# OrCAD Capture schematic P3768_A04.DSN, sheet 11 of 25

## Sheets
11 0014_USB3.1 HUB: size Custom
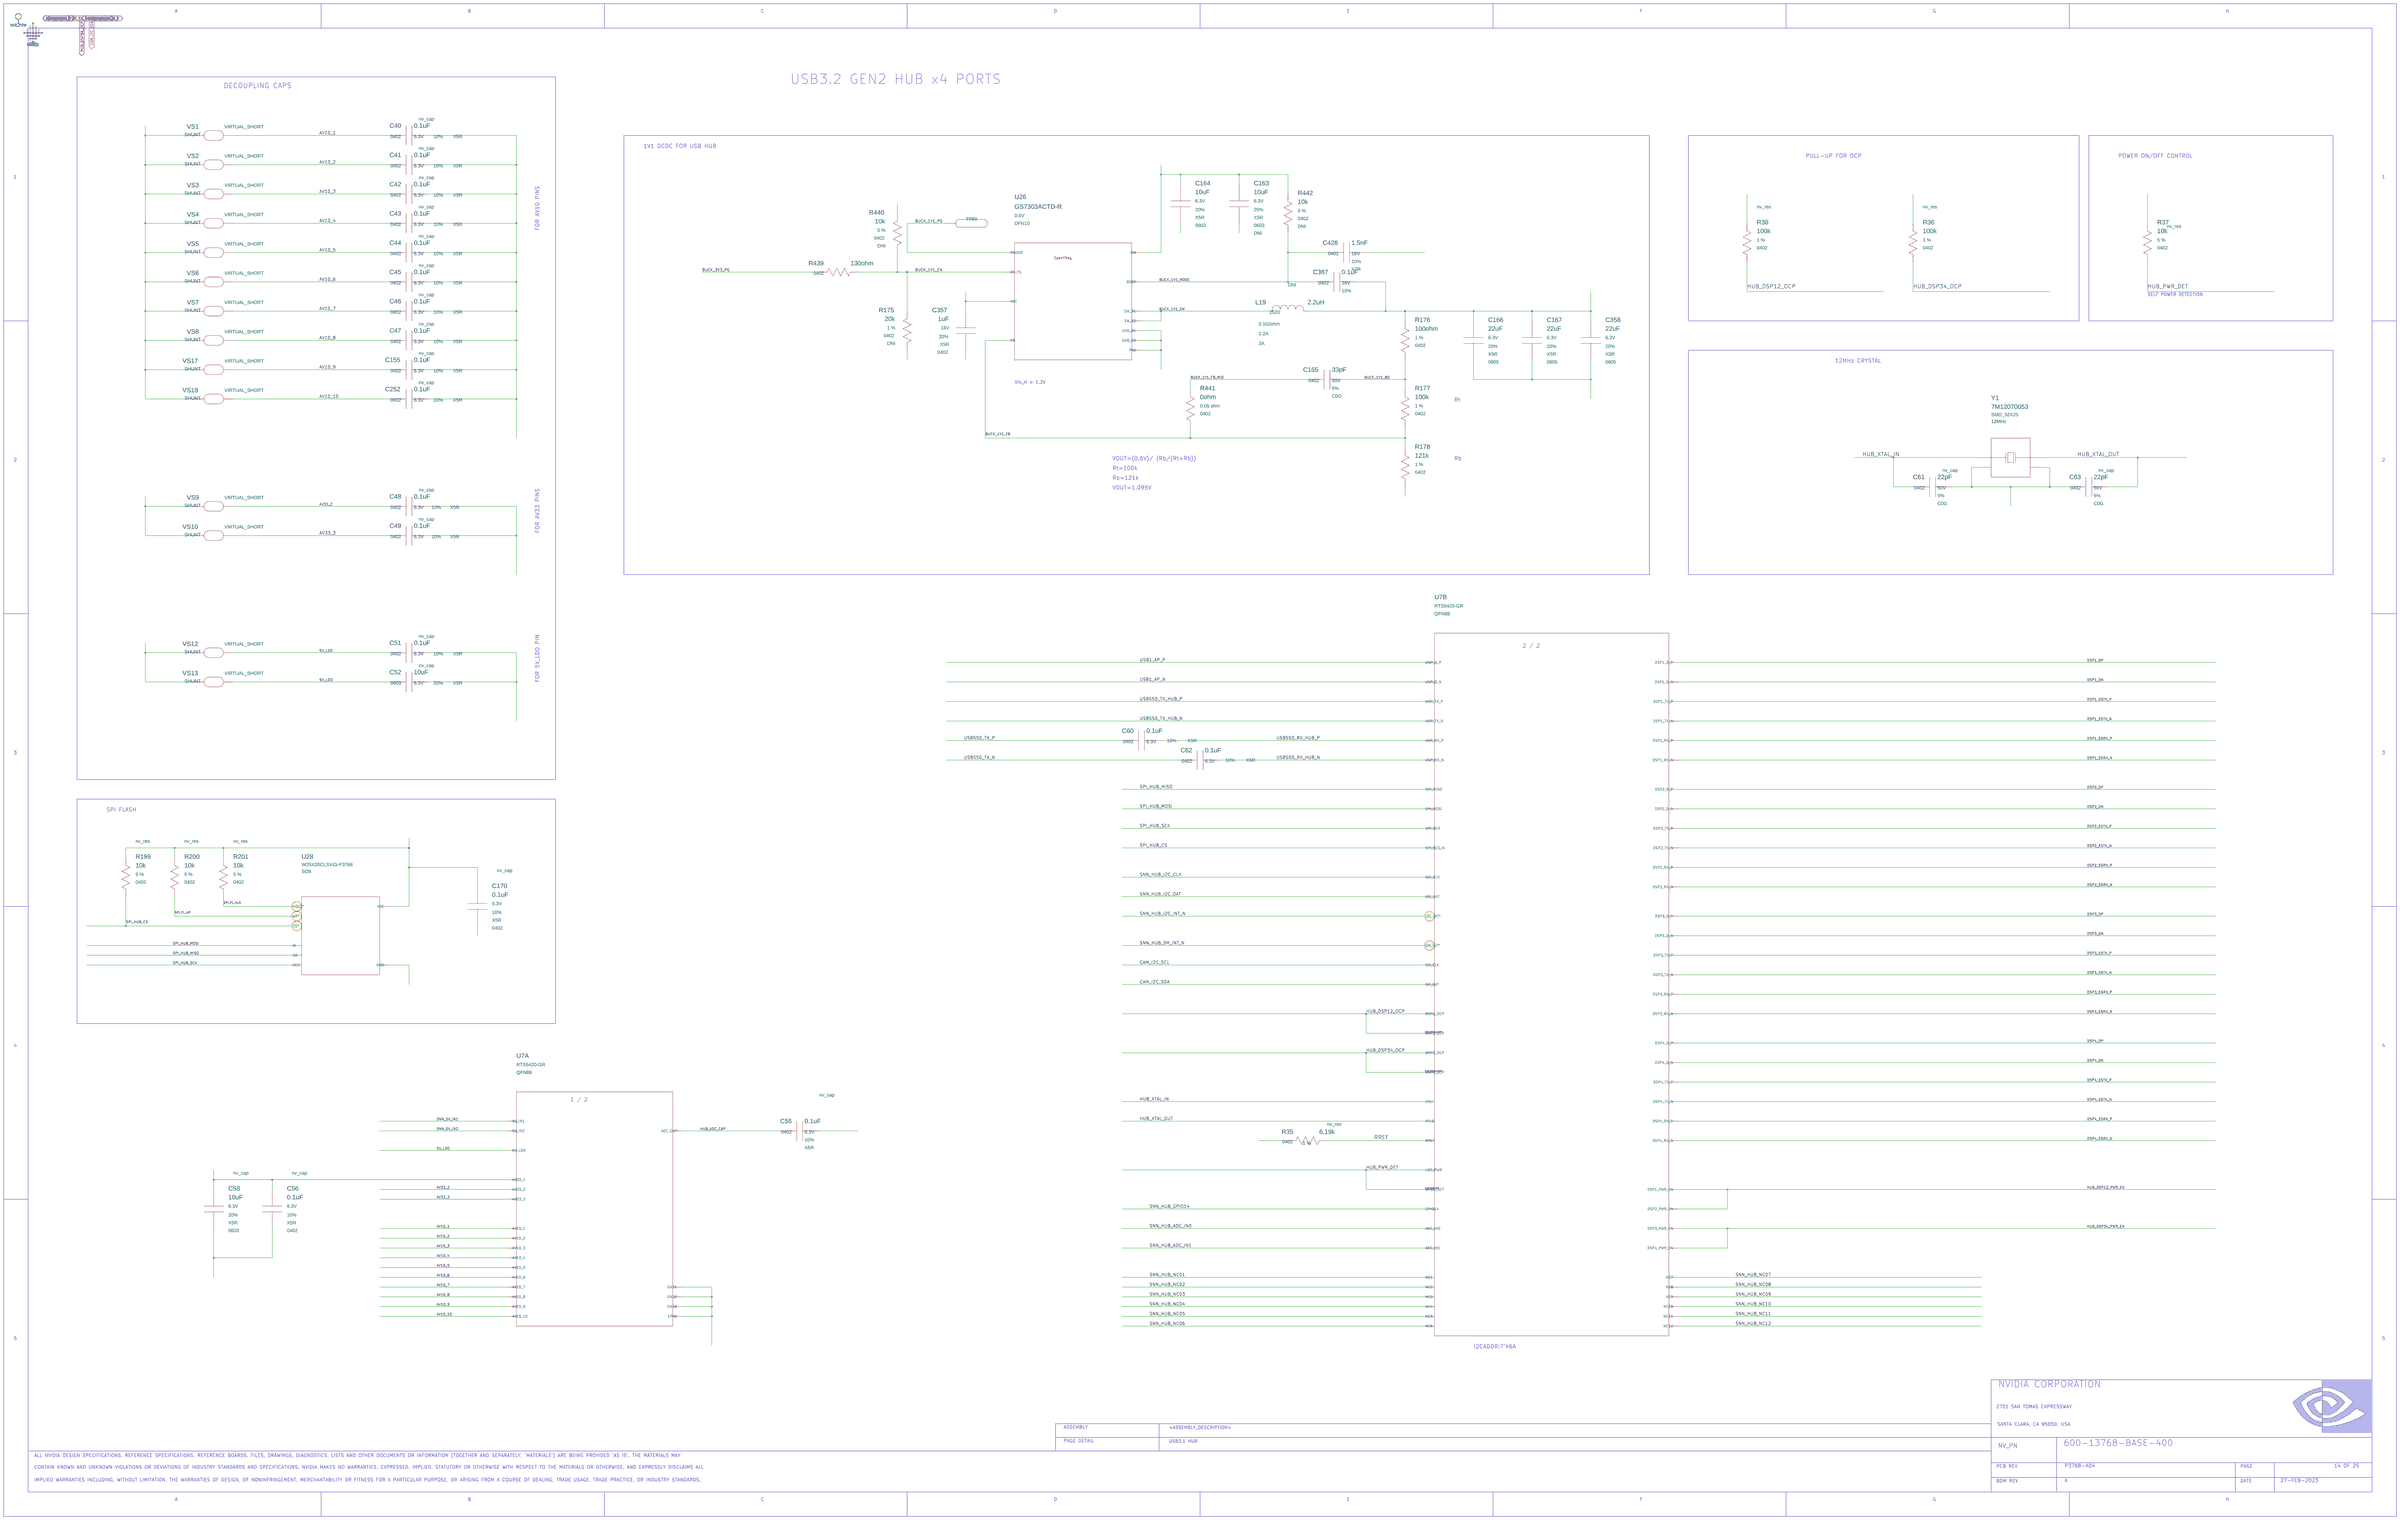
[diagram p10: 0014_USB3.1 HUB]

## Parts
C40  0.1uF  [0402]
C41  0.1uF  [0402]
C42  0.1uF  [0402]
C43  0.1uF  [0402]
C44  0.1uF  [0402]
C45  0.1uF  [0402]
C46  0.1uF  [0402]
C47  0.1uF  [0402]
C48  0.1uF  [0402]
C49  0.1uF  [0402]
C51  0.1uF  [0402]
C52  10uF  [0603]
C55  0.1uF  [0402]
C56  0.1uF  [0402]
C58  10uF  [0603]
C60  0.1uF  [0402]
C61  22pF  [0402]
C62  0.1uF  [0402]
C63  22pF  [0402]
C155  0.1uF  [0402]
C163  10uF  [0603]
C164  10uF  [0603]
C165  33pF  [0402]
C166  22uF  [0805U]
C167  22uF  [0805U]
C170  0.1uF  [0402]
C252  0.1uF  [0402]
C357  1uF  [0402]
C358  22uF  [0805U]
C387  0.1uF  [0402]
C428  1.5nF  [0402]
L19  2.2uH  [IND_NONRKO_SMD_025X020]
R35  6.19k  [0402]
R36  100k  [0402]
R37  10k  [0402]
R38  100k  [0402]
R175  20k  [0402]
R176  100ohm  [0402]
R177  100k  [0402]
R178  121k  [0402]
R199  10k  [0402]
R200  10k  [0402]
R201  10k  [0402]
R439  130ohm  [0402]
R440  10k  [0402]
R441  0ohm  [0402]
R442  10k  [0402]
TP50  LABTESTPOINT  [LTPT071C125D]
U7  U_USB_HUB_RTS5489  [QFN088Q_P040_0100_T069X069]  (sections A,B)
U26  0.6V  [DFN10_P050_030X030_T024X017]
U28  U_MEM_FL_SER_256KX8  [SO08_048X038]
VS1  VIRTUAL_SHORT  [VIRTUAL_SHORT]
VS2  VIRTUAL_SHORT  [VIRTUAL_SHORT]
VS3  VIRTUAL_SHORT  [VIRTUAL_SHORT]
VS4  VIRTUAL_SHORT  [VIRTUAL_SHORT]
VS5  VIRTUAL_SHORT  [VIRTUAL_SHORT]
VS6  VIRTUAL_SHORT  [VIRTUAL_SHORT]
VS7  VIRTUAL_SHORT  [VIRTUAL_SHORT]
VS8  VIRTUAL_SHORT  [VIRTUAL_SHORT]
VS9  VIRTUAL_SHORT  [VIRTUAL_SHORT]
VS10  VIRTUAL_SHORT  [VIRTUAL_SHORT]
VS12  VIRTUAL_SHORT  [VIRTUAL_SHORT]
VS13  VIRTUAL_SHORT  [VIRTUAL_SHORT]
VS17  VIRTUAL_SHORT  [VIRTUAL_SHORT]
VS18  VIRTUAL_SHORT  [VIRTUAL_SHORT]
Y1  12MHz  [XTAL_SMD_4_032X025_D]

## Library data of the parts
C40 = C: ASSEMBLY: USB3_TYPEA; CDS_LIB: discrete; CDS_PART_NAME: C_0402-0.1UF,X5R,10%,6.3V,039-0007-000; CDS_PHYS_PART_NAME: C_0402-0.1UF,X5R,10%,6.3V,039-0007-000-0.1UF,039-0007-000; CDS_SEC: 1; DEVICE_TYPENAME: C_0402-01UFX5R1063V039-0007-000-01UF039-0007-000; DRAWING: @P3768_A04_LIB.P3768_A04(SCH_1):PAGE14; MAT: X5R; MAX_VOLTAGE: 6.3V; NV_PN: 039-0007-000; PATH: I63; PHYS_PAGE: 14; PSPICETEMPLATE: X^@REFDES  %1    %2   @NV_PN; ROT: 0; SEC: 1; SIGNAL_MODEL: nv_cap; TOL: 10%; VER: 2; XY: (-10050,6950)
C41 = C: ASSEMBLY: USB3_TYPEA; CDS_LIB: discrete; CDS_PART_NAME: C_0402-0.1UF,X5R,10%,6.3V,039-0007-000; CDS_PHYS_PART_NAME: C_0402-0.1UF,X5R,10%,6.3V,039-0007-000-0.1UF,039-0007-000; CDS_SEC: 1; DEVICE_TYPENAME: C_0402-01UFX5R1063V039-0007-000-01UF039-0007-000; DRAWING: @P3768_A04_LIB.P3768_A04(SCH_1):PAGE14; MAT: X5R; MAX_VOLTAGE: 6.3V; NV_PN: 039-0007-000; PATH: I64; PHYS_PAGE: 14; PSPICETEMPLATE: X^@REFDES  %1    %2   @NV_PN; ROT: 0; SEC: 1; SIGNAL_MODEL: nv_cap; TOL: 10%; VER: 2; XY: (-10050,6800)
C42 = C: ASSEMBLY: USB3_TYPEA; CDS_LIB: discrete; CDS_PART_NAME: C_0402-0.1UF,X5R,10%,6.3V,039-0007-000; CDS_PHYS_PART_NAME: C_0402-0.1UF,X5R,10%,6.3V,039-0007-000-0.1UF,039-0007-000; CDS_SEC: 1; DEVICE_TYPENAME: C_0402-01UFX5R1063V039-0007-000-01UF039-0007-000; DRAWING: @P3768_A04_LIB.P3768_A04(SCH_1):PAGE14; MAT: X5R; MAX_VOLTAGE: 6.3V; NV_PN: 039-0007-000; PATH: I65; PHYS_PAGE: 14; PSPICETEMPLATE: X^@REFDES  %1    %2   @NV_PN; ROT: 0; SEC: 1; SIGNAL_MODEL: nv_cap; TOL: 10%; VER: 2; XY: (-10050,6650)
C43 = C: ASSEMBLY: USB3_TYPEA; CDS_LIB: discrete; CDS_PART_NAME: C_0402-0.1UF,X5R,10%,6.3V,039-0007-000; CDS_PHYS_PART_NAME: C_0402-0.1UF,X5R,10%,6.3V,039-0007-000-0.1UF,039-0007-000; CDS_SEC: 1; DEVICE_TYPENAME: C_0402-01UFX5R1063V039-0007-000-01UF039-0007-000; DRAWING: @P3768_A04_LIB.P3768_A04(SCH_1):PAGE14; MAT: X5R; MAX_VOLTAGE: 6.3V; NV_PN: 039-0007-000; PATH: I67; PHYS_PAGE: 14; PSPICETEMPLATE: X^@REFDES  %1    %2   @NV_PN; ROT: 0; SEC: 1; SIGNAL_MODEL: nv_cap; TOL: 10%; VER: 2; XY: (-10050,6500)
C44 = C: ASSEMBLY: USB3_TYPEA; CDS_LIB: discrete; CDS_PART_NAME: C_0402-0.1UF,X5R,10%,6.3V,039-0007-000; CDS_PHYS_PART_NAME: C_0402-0.1UF,X5R,10%,6.3V,039-0007-000-0.1UF,039-0007-000; CDS_SEC: 1; DEVICE_TYPENAME: C_0402-01UFX5R1063V039-0007-000-01UF039-0007-000; DRAWING: @P3768_A04_LIB.P3768_A04(SCH_1):PAGE14; MAT: X5R; MAX_VOLTAGE: 6.3V; NV_PN: 039-0007-000; PATH: I66; PHYS_PAGE: 14; PSPICETEMPLATE: X^@REFDES  %1    %2   @NV_PN; ROT: 0; SEC: 1; SIGNAL_MODEL: nv_cap; TOL: 10%; VER: 2; XY: (-10050,6350)
C45 = C: ASSEMBLY: USB3_TYPEA; CDS_LIB: discrete; CDS_PART_NAME: C_0402-0.1UF,X5R,10%,6.3V,039-0007-000; CDS_PHYS_PART_NAME: C_0402-0.1UF,X5R,10%,6.3V,039-0007-000-0.1UF,039-0007-000; CDS_SEC: 1; DEVICE_TYPENAME: C_0402-01UFX5R1063V039-0007-000-01UF039-0007-000; DRAWING: @P3768_A04_LIB.P3768_A04(SCH_1):PAGE14; MAT: X5R; MAX_VOLTAGE: 6.3V; NV_PN: 039-0007-000; PATH: I70; PHYS_PAGE: 14; PSPICETEMPLATE: X^@REFDES  %1    %2   @NV_PN; ROT: 0; SEC: 1; SIGNAL_MODEL: nv_cap; TOL: 10%; VER: 2; XY: (-10050,6200)
C46 = C: ASSEMBLY: USB3_TYPEA; CDS_LIB: discrete; CDS_PART_NAME: C_0402-0.1UF,X5R,10%,6.3V,039-0007-000; CDS_PHYS_PART_NAME: C_0402-0.1UF,X5R,10%,6.3V,039-0007-000-0.1UF,039-0007-000; CDS_SEC: 1; DEVICE_TYPENAME: C_0402-01UFX5R1063V039-0007-000-01UF039-0007-000; DRAWING: @P3768_A04_LIB.P3768_A04(SCH_1):PAGE14; MAT: X5R; MAX_VOLTAGE: 6.3V; NV_PN: 039-0007-000; PATH: I71; PHYS_PAGE: 14; PSPICETEMPLATE: X^@REFDES  %1    %2   @NV_PN; ROT: 0; SEC: 1; SIGNAL_MODEL: nv_cap; TOL: 10%; VER: 2; XY: (-10050,6050)
C47 = C: ASSEMBLY: USB3_TYPEA; CDS_LIB: discrete; CDS_PART_NAME: C_0402-0.1UF,X5R,10%,6.3V,039-0007-000; CDS_PHYS_PART_NAME: C_0402-0.1UF,X5R,10%,6.3V,039-0007-000-0.1UF,039-0007-000; CDS_SEC: 1; DEVICE_TYPENAME: C_0402-01UFX5R1063V039-0007-000-01UF039-0007-000; DRAWING: @P3768_A04_LIB.P3768_A04(SCH_1):PAGE14; MAT: X5R; MAX_VOLTAGE: 6.3V; NV_PN: 039-0007-000; PATH: I72; PHYS_PAGE: 14; PSPICETEMPLATE: X^@REFDES  %1    %2   @NV_PN; ROT: 0; SEC: 1; SIGNAL_MODEL: nv_cap; TOL: 10%; VER: 2; XY: (-10050,5900)
C48 = C: ASSEMBLY: USB3_TYPEA; CDS_LIB: discrete; CDS_PART_NAME: C_0402-0.1UF,X5R,10%,6.3V,039-0007-000; CDS_PHYS_PART_NAME: C_0402-0.1UF,X5R,10%,6.3V,039-0007-000-0.1UF,039-0007-000; CDS_SEC: 1; DEVICE_TYPENAME: C_0402-01UFX5R1063V039-0007-000-01UF039-0007-000; DRAWING: @P3768_A04_LIB.P3768_A04(SCH_1):PAGE14; MAT: X5R; MAX_VOLTAGE: 6.3V; NV_PN: 039-0007-000; PATH: I73; PHYS_PAGE: 14; PSPICETEMPLATE: X^@REFDES  %1    %2   @NV_PN; ROT: 0; SEC: 1; SIGNAL_MODEL: nv_cap; TOL: 10%; VER: 2; XY: (-10050,5050)
C49 = C: ASSEMBLY: USB3_TYPEA; CDS_LIB: discrete; CDS_PART_NAME: C_0402-0.1UF,X5R,10%,6.3V,039-0007-000; CDS_PHYS_PART_NAME: C_0402-0.1UF,X5R,10%,6.3V,039-0007-000-0.1UF,039-0007-000; CDS_SEC: 1; DEVICE_TYPENAME: C_0402-01UFX5R1063V039-0007-000-01UF039-0007-000; DRAWING: @P3768_A04_LIB.P3768_A04(SCH_1):PAGE14; MAT: X5R; MAX_VOLTAGE: 6.3V; NV_PN: 039-0007-000; PATH: I74; PHYS_PAGE: 14; PSPICETEMPLATE: X^@REFDES  %1    %2   @NV_PN; ROT: 0; SEC: 1; SIGNAL_MODEL: nv_cap; TOL: 10%; VER: 2; XY: (-10050,4900)
C51 = C: ASSEMBLY: USB3_TYPEA; CDS_LIB: discrete; CDS_PART_NAME: C_0402-0.1UF,X5R,10%,6.3V,039-0007-000; CDS_PHYS_PART_NAME: C_0402-0.1UF,X5R,10%,6.3V,039-0007-000-0.1UF,039-0007-000; CDS_SEC: 1; DEVICE_TYPENAME: C_0402-01UFX5R1063V039-0007-000-01UF039-0007-000; DRAWING: @P3768_A04_LIB.P3768_A04(SCH_1):PAGE14; MAT: X5R; MAX_VOLTAGE: 6.3V; NV_PN: 039-0007-000; PATH: I77; PHYS_PAGE: 14; PSPICETEMPLATE: X^@REFDES  %1    %2   @NV_PN; ROT: 0; SEC: 1; SIGNAL_MODEL: nv_cap; TOL: 10%; VER: 2; XY: (-10050,4300)
C52 = C: ASSEMBLY: USB3_TYPEA; CDS_LIB: discrete; CDS_PART_NAME: C_0603-10UF,X5R,20%,6.3V,032-2136-000; CDS_PHYS_PART_NAME: C_0603-10UF,X5R,20%,6.3V,032-2136-000-032-2136-000,10UF; CDS_SEC: 1; DEVICE_TYPENAME: C_0603-10UFX5R2063V032-2136-000-032-2136-00010UF; DRAWING: @P3768_A04_LIB.P3768_A04(SCH_1):PAGE14; MAT: X5R; MAX_VOLTAGE: 6.3V; NV_PN: 032-2136-000; PATH: I76; PHYS_PAGE: 14; PSPICETEMPLATE: X^@REFDES  %1    %2   @NV_PN; ROT: 0; SEC: 1; SIGNAL_MODEL: nv_cap; TOL: 20%; VER: 2; XY: (-10050,4150)
C55 = C: ASSEMBLY: USB3_TYPEA; CDS_LIB: discrete; CDS_PART_NAME: C_0402-0.1UF,X5R,10%,6.3V,039-0007-000; CDS_PHYS_PART_NAME: C_0402-0.1UF,X5R,10%,6.3V,039-0007-000-0.1UF,039-0007-000; CDS_SEC: 1; DEVICE_TYPENAME: C_0402-01UFX5R1063V039-0007-000-01UF039-0007-000; DRAWING: @P3768_A04_LIB.P3768_A04(SCH_1):PAGE14; MAT: X5R; MAX_VOLTAGE: 6.3V; NV_PN: 039-0007-000; PATH: I100; PHYS_PAGE: 14; PSPICETEMPLATE: X^@REFDES  %1    %2   @NV_PN; ROT: 0; SEC: 1; SIGNAL_MODEL: nv_cap; TOL: 10%; VER: 2; XY: (-8050,1850)
C56 = C#1: ASSEMBLY: USB3_TYPEA; CDS_LIB: discrete; CDS_PART_NAME: C_0402-0.1UF,X5R,10%,6.3V,039-0007-000; CDS_PHYS_PART_NAME: C_0402-0.1UF,X5R,10%,6.3V,039-0007-000-0.1UF,039-0007-000; CDS_SEC: 1; CHIPS_PART_NAME: C; DEVICE_TYPENAME: C_0402-01UFX5R1063V039-0007-000-01UF039-0007-000; DRAWING: @P3768_A04_LIB.P3768_A04(SCH_1):PAGE14; MAT: X5R; MAX_VOLTAGE: 6.3V; NV_PN: 039-0007-000; PATH: I105; PHYS_PAGE: 14; PSPICETEMPLATE: X^@REFDES  %1    %2   @NV_PN; ROT: 0; SEC: 1; SIGNAL_MODEL: nv_cap; TOL: 10%; VER: 1; XY: (-10750,1450)
C58 = C#1: ASSEMBLY: USB3_TYPEA; CDS_LIB: discrete; CDS_PART_NAME: C_0603-10UF,X5R,20%,6.3V,032-2136-000; CDS_PHYS_PART_NAME: C_0603-10UF,X5R,20%,6.3V,032-2136-000-032-2136-000,10UF; CDS_SEC: 1; CHIPS_PART_NAME: C; DEVICE_TYPENAME: C_0603-10UFX5R2063V032-2136-000-032-2136-00010UF; DRAWING: @P3768_A04_LIB.P3768_A04(SCH_1):PAGE14; MAT: X5R; MAX_VOLTAGE: 6.3V; NV_PN: 032-2136-000; PATH: I102; PHYS_PAGE: 14; PSPICETEMPLATE: X^@REFDES  %1    %2   @NV_PN; ROT: 0; SEC: 1; SIGNAL_MODEL: nv_cap; TOL: 20%; VER: 1; XY: (-11050,1450)
C60 = C: ASSEMBLY: USB3_TYPEA; CDS_LIB: discrete; CDS_PART_NAME: C_0402-0.1UF,X5R,10%,6.3V,039-0007-000; CDS_PHYS_PART_NAME: C_0402-0.1UF,X5R,10%,6.3V,039-0007-000-0.1UF,039-0007-000; CDS_SEC: 1; DEVICE_TYPENAME: C_0402-01UFX5R1063V039-0007-000-01UF039-0007-000; DRAWING: @P3768_A04_LIB.P3768_A04(SCH_1):PAGE14; MAT: X5R; MAX_VOLTAGE: 6.3V; NV_PN: 039-0007-000; PATH: I138; PHYS_PAGE: 14; PSPICETEMPLATE: X^@REFDES  %1    %2   @NV_PN; ROT: 0; SEC: 1; SIGNAL_MODEL: nv_cap; TOL: 10%; VER: 2; XY: (-6300,3850)
C61 = C: ASSEMBLY: USB3_TYPEA; CDS_LIB: discrete; CDS_PART_NAME: C_0402-22PF,C0G,5%,50V,035-0023-000; CDS_PHYS_PART_NAME: C_0402-22PF,C0G,5%,50V,035-0023-000-035-0023-000,22PF; CDS_SEC: 1; DEVICE_TYPENAME: C_0402-22PFC0G550V035-0023-000-035-0023-00022PF; DRAWING: @P3768_A04_LIB.P3768_A04(SCH_1):PAGE14; MAT: C0G; MAX_VOLTAGE: 50V; NV_PN: 035-0023-000; PATH: I15; PHYS_PAGE: 14; PSPICETEMPLATE: X^@REFDES  %1    %2   @NV_PN; ROT: 0; SEC: 1; SIGNAL_MODEL: nv_cap; TOL: 5%; VER: 2; XY: (-2250,5150)
C62 = C: ASSEMBLY: USB3_TYPEA; CDS_LIB: discrete; CDS_PART_NAME: C_0402-0.1UF,X5R,10%,6.3V,039-0007-000; CDS_PHYS_PART_NAME: C_0402-0.1UF,X5R,10%,6.3V,039-0007-000-0.1UF,039-0007-000; CDS_SEC: 1; DEVICE_TYPENAME: C_0402-01UFX5R1063V039-0007-000-01UF039-0007-000; DRAWING: @P3768_A04_LIB.P3768_A04(SCH_1):PAGE14; MAT: X5R; MAX_VOLTAGE: 6.3V; NV_PN: 039-0007-000; PATH: I137; PHYS_PAGE: 14; PSPICETEMPLATE: X^@REFDES  %1    %2   @NV_PN; ROT: 0; SEC: 1; SIGNAL_MODEL: nv_cap; TOL: 10%; VER: 2; XY: (-6000,3750)
C63 = C: ASSEMBLY: USB3_TYPEA; CDS_LIB: discrete; CDS_PART_NAME: C_0402-22PF,C0G,5%,50V,035-0023-000; CDS_PHYS_PART_NAME: C_0402-22PF,C0G,5%,50V,035-0023-000-035-0023-000,22PF; CDS_SEC: 1; DEVICE_TYPENAME: C_0402-22PFC0G550V035-0023-000-035-0023-00022PF; DRAWING: @P3768_A04_LIB.P3768_A04(SCH_1):PAGE14; MAT: C0G; MAX_VOLTAGE: 50V; NV_PN: 035-0023-000; PATH: I11; PHYS_PAGE: 14; PSPICETEMPLATE: X^@REFDES  %1    %2   @NV_PN; ROT: 0; SEC: 1; SIGNAL_MODEL: nv_cap; TOL: 5%; VER: 2; XY: (-1450,5150)
C155 = C: ASSEMBLY: USB3_TYPEA; CDS_LIB: discrete; CDS_PART_NAME: C_0402-0.1UF,X5R,10%,6.3V,039-0007-000; CDS_PHYS_PART_NAME: C_0402-0.1UF,X5R,10%,6.3V,039-0007-000-0.1UF,039-0007-000; CDS_SEC: 1; DEVICE_TYPENAME: C_0402-01UFX5R1063V039-0007-000-01UF039-0007-000; DRAWING: @P3768_A04_LIB.P3768_A04(SCH_1):PAGE14; MAT: X5R; MAX_VOLTAGE: 6.3V; NV_PN: 039-0007-000; PATH: I149; PHYS_PAGE: 14; PSPICETEMPLATE: X^@REFDES  %1    %2   @NV_PN; ROT: 0; SEC: 1; SIGNAL_MODEL: nv_cap; TOL: 10%; VER: 2; XY: (-10050,5750)
C163 = C#1: ASSEMBLY: 1V1_DCDC; CDS_LIB: discrete; CDS_PART_NAME: C_0603-10UF,X5R,20%,6.3V,032-2136-000; CDS_PHYS_PART_NAME: C_0603-10UF,X5R,20%,6.3V,032-2136-000-032-2136-000,10UF; CDS_SEC: 1; CHIPS_PART_NAME: C; DEVICE_TYPENAME: C_0603-10UFX5R2063V032-2136-000-032-2136-00010UF; DRAWING: @P3768_A04_LIB.P3768_A04(SCH_1):PAGE14; MAT: X5R; MAX_VOLTAGE: 6.3V; NV_PN: 032-2136-000; PATH: I233; PHYS_PAGE: 14; PSPICETEMPLATE: X^@REFDES  %1    %2   @NV_PN; ROT: 0; SEC: 1; SIGNAL_MODEL: nv_cap; SKU: DNI; TOL: 20%; VER: 1; XY: (-5800,6600)
C164 = C#1: ASSEMBLY: 1V1_DCDC; CDS_LIB: discrete; CDS_PART_NAME: C_0603-10UF,X5R,20%,6.3V,032-2136-000; CDS_PHYS_PART_NAME: C_0603-10UF,X5R,20%,6.3V,032-2136-000-032-2136-000,10UF; CDS_SEC: 1; CHIPS_PART_NAME: C; DEVICE_TYPENAME: C_0603-10UFX5R2063V032-2136-000-032-2136-00010UF; DRAWING: @P3768_A04_LIB.P3768_A04(SCH_1):PAGE14; MAT: X5R; MAX_VOLTAGE: 6.3V; NV_PN: 032-2136-000; PATH: I230; PHYS_PAGE: 14; PSPICETEMPLATE: X^@REFDES  %1    %2   @NV_PN; ROT: 0; SEC: 1; SIGNAL_MODEL: nv_cap; TOL: 20%; VER: 1; XY: (-6100,6600)
C165 = C: ASSEMBLY: 1V1_DCDC; CDS_LIB: discrete; CDS_PART_NAME: C_0402-33PF,C0G,5%,50V,035-0028-000; CDS_PHYS_PART_NAME: C_0402-33PF,C0G,5%,50V,035-0028-000-035-0028-000,33PF; CDS_SEC: 1; DEVICE_TYPENAME: C_0402-33PFC0G550V035-0028-000-035-0028-00033PF; DRAWING: @P3768_A04_LIB.P3768_A04(SCH_1):PAGE14; MAT: C0G; MAX_VOLTAGE: 50V; NV_PN: 035-0028-000; PATH: I222; PHYS_PAGE: 14; ROT: 0; SEC: 1; SIGNAL_MODEL: nv_cap; TOL: 5%; VER: 2; XY: (-5350,5700)
C166 = C#1: ASSEMBLY: 1V1_DCDC; CDS_LIB: discrete; CDS_PART_NAME: C_0805-22UF,X5R,20%,6.3V,039-0127-000; CDS_PHYS_PART_NAME: C_0805-22UF,X5R,20%,6.3V,039-0127-000-039-0127-000,22UF; CDS_SEC: 1; CHIPS_PART_NAME: C; DEVICE_TYPENAME: C_0805-22UFX5R2063V039-0127-000-039-0127-00022UF; DRAWING: @P3768_A04_LIB.P3768_A04(SCH_1):PAGE14; MAT: X5R; MAX_VOLTAGE: 6.3V; NV_PN: 039-0127-000; PACK_TYPE: 0805; PATH: I258; PHYS_PAGE: 14; PSPICETEMPLATE: X^@REFDES  %1    %2   @NV_PN; ROT: 0; SEC: 1; SIGNAL_MODEL: nv_cap; TOL: 20%; VER: 1; XY: (-4600,5900)
C167 = C#1: ASSEMBLY: 1V1_DCDC; CDS_LIB: discrete; CDS_PART_NAME: C_0805-22UF,X5R,20%,6.3V,039-0127-000; CDS_PHYS_PART_NAME: C_0805-22UF,X5R,20%,6.3V,039-0127-000-039-0127-000,22UF; CDS_SEC: 1; CHIPS_PART_NAME: C; DEVICE_TYPENAME: C_0805-22UFX5R2063V039-0127-000-039-0127-00022UF; DRAWING: @P3768_A04_LIB.P3768_A04(SCH_1):PAGE14; MAT: X5R; MAX_VOLTAGE: 6.3V; NV_PN: 039-0127-000; PACK_TYPE: 0805; PATH: I259; PHYS_PAGE: 14; PSPICETEMPLATE: X^@REFDES  %1    %2   @NV_PN; ROT: 0; SEC: 1; SIGNAL_MODEL: nv_cap; TOL: 20%; VER: 1; XY: (-4300,5900)
C170 = C#1: ASSEMBLY: USB3_TYPEA; CDS_LIB: discrete; CDS_PART_NAME: C_0402-0.1UF,X5R,10%,6.3V,039-0007-000; CDS_PHYS_PART_NAME: C_0402-0.1UF,X5R,10%,6.3V,039-0007-000-0.1UF,039-0007-000; CDS_SEC: 1; CHIPS_PART_NAME: C; DEVICE_TYPENAME: C_0402-01UFX5R1063V039-0007-000-01UF039-0007-000; DRAWING: @P3768_A04_LIB.P3768_A04(SCH_1):PAGE14; MAT: X5R; MAX_VOLTAGE: 6.3V; NV_PN: 039-0007-000; PATH: I199; PHYS_PAGE: 14; PSPICETEMPLATE: X^@REFDES  %1    %2   @NV_PN; ROT: 0; SEC: 1; SIGNAL_MODEL: nv_cap; TOL: 10%; VER: 1; XY: (-9700,3000)
C252 = C: ASSEMBLY: USB3_TYPEA; CDS_LIB: discrete; CDS_PART_NAME: C_0402-0.1UF,X5R,10%,6.3V,039-0007-000; CDS_PHYS_PART_NAME: C_0402-0.1UF,X5R,10%,6.3V,039-0007-000-0.1UF,039-0007-000; CDS_SEC: 1; DEVICE_TYPENAME: C_0402-01UFX5R1063V039-0007-000-01UF039-0007-000; DRAWING: @P3768_A04_LIB.P3768_A04(SCH_1):PAGE14; MAT: X5R; MAX_VOLTAGE: 6.3V; NV_PN: 039-0007-000; PATH: I150; PHYS_PAGE: 14; PSPICETEMPLATE: X^@REFDES  %1    %2   @NV_PN; ROT: 0; SEC: 1; SIGNAL_MODEL: nv_cap; TOL: 10%; VER: 2; XY: (-10050,5600)
C357 = C#1: ASSEMBLY: 1V1_DCDC; CDS_LIB: discrete; CDS_PART_NAME: C_0402-1UF,X5R,20%,16V,032-0521-000; CDS_PHYS_PART_NAME: C_0402-1UF,X5R,20%,16V,032-0521-000-032-0521-000,1UF; CDS_SEC: 1; CHIPS_PART_NAME: C; DEVICE_TYPENAME: C_0402-1UFX5R2016V032-0521-000-032-0521-0001UF; DRAWING: @P3768_A04_LIB.P3768_A04(SCH_1):PAGE14; MAT: X5R; MAX_VOLTAGE: 16V; NV_PN: 032-0521-000; PATH: I256; PHYS_PAGE: 14; PSPICETEMPLATE: X^@REFDES  %1    %2   @NV_PN; ROT: 2; SEC: 1; SIGNAL_MODEL: nv_cap; TOL: 20%; VER: 1; XY: (-7200,5950)
C358 = C#1: ASSEMBLY: 1V1_DCDC; CDS_LIB: discrete; CDS_PART_NAME: C_0805-22UF,X5R,20%,6.3V,039-0127-000; CDS_PHYS_PART_NAME: C_0805-22UF,X5R,20%,6.3V,039-0127-000-039-0127-000,22UF; CDS_SEC: 1; CHIPS_PART_NAME: C; DEVICE_TYPENAME: C_0805-22UFX5R2063V039-0127-000-039-0127-00022UF; DRAWING: @P3768_A04_LIB.P3768_A04(SCH_1):PAGE14; MAT: X5R; MAX_VOLTAGE: 6.3V; NV_PN: 039-0127-000; PACK_TYPE: 0805; PATH: I262; PHYS_PAGE: 14; PSPICETEMPLATE: X^@REFDES  %1    %2   @NV_PN; ROT: 0; SEC: 1; SIGNAL_MODEL: nv_capp; TOL: 20%; VER: 1; XY: (-4000,5900)
C387 = C: ASSEMBLY: 1V1_DCDC; CDS_LIB: discrete; CDS_PART_NAME: C_0402-0.1UF,X7R,10%,16V,032-0793-000; CDS_PHYS_PART_NAME: C_0402-0.1UF,X7R,10%,16V,032-0793-000-0.1UF,032-0793-000; CDS_SEC: 1; DEVICE_TYPENAME: C_0402-01UFX7R1016V032-0793-000-01UF032-0793-000; DRAWING: @P3768_A04_LIB.P3768_A04(SCH_1):PAGE14; MAT: X7R; MAX_VOLTAGE: 16V; NV_PN: 032-0793-000; PATH: I235; PHYS_PAGE: 14; PSPICETEMPLATE: X^@REFDES  %1    %2   @NV_PN; ROT: 0; SEC: 1; SIGNAL_MODEL: nv_cap; SKU: DNI; TOL: 10%; VER: 2; XY: (-5300,6200)
C428 = C: ASSEMBLY: 1V1_DCDC; CDS_LIB: discrete; CDS_PART_NAME: C_0402-1.5NF,X7R,10%,16V,036-0241-000; CDS_PHYS_PART_NAME: C_0402-1.5NF,X7R,10%,16V,036-0241-000-036-0241-000,1.5NF; CDS_SEC: 1; DEVICE_TYPENAME: C_0402-15NFX7R1016V036-0241-000-036-0241-00015NF; DRAWING: @P3768_A04_LIB.P3768_A04(SCH_1):PAGE14; MAT: X7R; MAX_VOLTAGE: 16V; NV_PN: 036-0241-000; PATH: I275; PHYS_PAGE: 14; ROT: 0; SEC: 1; SIGNAL_MODEL: nv_cap; TOL: 10%; VER: 2; XY: (-5250,6350)
L19 = L: ASSEMBLY: 1V1_DCDC; CDS_LIB: discrete; CDS_PART_NAME: L_2520-2.2UH,METAL DUST,20%,2.2A,3A,0.102OHM,0@0HZ,0HZ,130-1221-000; CDS_PHYS_PART_NAME: L_2520-2.2UH,METAL DUST,20%,2.2A,3A,0.102OHM,0@0HZ,0HZ,130-1221-000-130-1221-000,2.2UH; CDS_SEC: 1; CONTINUOUS_CURRENT: 2.2A; DC_RESISTANCE: 0.102ohm; DEVICE_TYPENAME: L_2520-22UHMETALDUST2022A3A0102OHM00HZ0HZ130-1221-000-130-1221-00022UH; DRAWING: @P3768_A04_LIB.P3768_A04(SCH_1):PAGE14; MAT: METAL DUST; MAX_CURRENT: 3A; NV_PN: 130-1221-000; PACK_TYPE: 2520; PATH: I232; PHYS_PAGE: 14; PSPICETEMPLATE: X^@REFDES  %1    %2   @NV_PN; Q: 0@0Hz; ROT: 0; SEC: 1; SELF_RESONANCE_FREQ: 0Hz; SIGNAL_MODEL: nv_ind; TOL: 20%; VER: 1; XY: (-5550,6050)
R35 = R#1: ASSEMBLY: USB3_TYPEA; CDS_LIB: discrete; CDS_PART_NAME: R_0402-6.19K,1 %,62.5MW,195-0384-000; CDS_PHYS_PART_NAME: R_0402-6.19K,1 %,62.5MW,195-0384-000-195-0384-000,6.19K; CDS_SEC: 1; CHIPS_PART_NAME: R; DEVICE_TYPENAME: R_0402-619K1625MW195-0384-000-195-0384-000619K; DRAWING: @P3768_A04_LIB.P3768_A04(SCH_1):PAGE14; MAX_WATTAGE: 62.5mW; NV_PN: 195-0384-000; PATH: I139; PHYS_PAGE: 14; PSPICETEMPLATE: X^@REFDES  %1    %2   @NV_PN; ROT: 0; SEC: 1; SIGNAL_MODEL: nv_res; TOL: 1 %; VER: 1; XY: (-5450,1800)
R36 = R: ASSEMBLY: USB3_TYPEA; CDS_LIB: discrete; CDS_PART_NAME: R_0402-100K,1 %,62.5MW,195-0005-000; CDS_PHYS_PART_NAME: R_0402-100K,1 %,62.5MW,195-0005-000-100K,195-0005-000; CDS_SEC: 1; DEVICE_TYPENAME: R_0402-100K1625MW195-0005-000-100K195-0005-000; DRAWING: @P3768_A04_LIB.P3768_A04(SCH_1):PAGE14; MAX_WATTAGE: 62.5mW; NV_PN: 195-0005-000; PATH: I49; PHYS_PAGE: 14; PSPICETEMPLATE: X^@REFDES  %1    %2   @NV_PN; ROT: 0; SEC: 1; SIGNAL_MODEL: nv_res; TOL: 1 %; VER: 2; XY: (-2350,6400)
R37 = R: ASSEMBLY: USB3_TYPEA; CDS_LIB: discrete; CDS_PART_NAME: R_0402-10K,5 %,62.5MW,195-0486-000; CDS_PHYS_PART_NAME: R_0402-10K,5 %,62.5MW,195-0486-000-10K,195-0486-000; CDS_SEC: 1; DEVICE_TYPENAME: R_0402-10K5625MW195-0486-000-10K195-0486-000; DRAWING: @P3768_A04_LIB.P3768_A04(SCH_1):PAGE14; MAX_WATTAGE: 62.5mW; NV_PN: 195-0486-000; PATH: I46; PHYS_PAGE: 14; PSPICETEMPLATE: X^@REFDES  %1    %2   @NV_PN; ROT: 0; SEC: 1; SIGNAL_MODEL: nv_res; TOL: 5 %; VER: 2; XY: (-1150,6400)
R38 = R: ASSEMBLY: USB3_TYPEA; CDS_LIB: discrete; CDS_PART_NAME: R_0402-100K,1 %,62.5MW,195-0005-000; CDS_PHYS_PART_NAME: R_0402-100K,1 %,62.5MW,195-0005-000-100K,195-0005-000; CDS_SEC: 1; DEVICE_TYPENAME: R_0402-100K1625MW195-0005-000-100K195-0005-000; DRAWING: @P3768_A04_LIB.P3768_A04(SCH_1):PAGE14; MAX_WATTAGE: 62.5mW; NV_PN: 195-0005-000; PATH: I166; PHYS_PAGE: 14; PSPICETEMPLATE: X^@REFDES  %1    %2   @NV_PN; ROT: 0; SEC: 1; SIGNAL_MODEL: nv_res; TOL: 1 %; VER: 2; XY: (-3200,6400)
R175 = R: ASSEMBLY: 1V1_DCDC; CDS_LIB: discrete; CDS_PART_NAME: R_0402-20K,1 %,62.5MW,195-0150-000; CDS_PHYS_PART_NAME: R_0402-20K,1 %,62.5MW,195-0150-000-195-0150-000,20K; CDS_SEC: 1; DEVICE_TYPENAME: R_0402-20K1625MW195-0150-000-195-0150-00020K; DRAWING: @P3768_A04_LIB.P3768_A04(SCH_1):PAGE14; MAX_WATTAGE: 62.5mW; NV_PN: 195-0150-000; PATH: I250; PHYS_PAGE: 14; PSPICETEMPLATE: X^@REFDES  %1    %2   @NV_PN; ROT: 2; SEC: 1; SIGNAL_MODEL: nv_res; SKU: DNI; TOL: 1 %; VER: 2; XY: (-7500,5950)
R176 = R: ASSEMBLY: 1V1_DCDC; CDS_LIB: discrete; CDS_PART_NAME: R_0402-100OHM,1 %,62.5MW,195-0002-000; CDS_PHYS_PART_NAME: R_0402-100OHM,1 %,62.5MW,195-0002-000-100OHM,195-0002-000; CDS_SEC: 1; DEVICE_TYPENAME: R_0402-100OHM1625MW195-0002-000-100OHM195-0002-000; DRAWING: @P3768_A04_LIB.P3768_A04(SCH_1):PAGE14; MAX_WATTAGE: 62.5mW; NV_PN: 195-0002-000; PATH: I245; PHYS_PAGE: 14; PSPICETEMPLATE: X^@REFDES  %1    %2   @NV_PN; ROT: 0; SEC: 1; SIGNAL_MODEL: nv_res; TOL: 1 %; VER: 2; XY: (-4950,5900)
R177 = R: ASSEMBLY: 1V1_DCDC; CDS_LIB: discrete; CDS_PART_NAME: R_0402-100K,1 %,62.5MW,195-0005-000; CDS_PHYS_PART_NAME: R_0402-100K,1 %,62.5MW,195-0005-000-100K,195-0005-000; CDS_SEC: 1; DEVICE_TYPENAME: R_0402-100K1625MW195-0005-000-100K195-0005-000; DRAWING: @P3768_A04_LIB.P3768_A04(SCH_1):PAGE14; MAX_WATTAGE: 62.5mW; NV_PN: 195-0005-000; PATH: I243; PHYS_PAGE: 14; PSPICETEMPLATE: X^@REFDES  %1    %2   @NV_PN; ROT: 0; SEC: 1; SIGNAL_MODEL: nv_res; TOL: 1 %; VER: 2; XY: (-4950,5550)
R178 = R: ASSEMBLY: 1V1_DCDC; CDS_LIB: discrete; CDS_PART_NAME: R_0402-121K,1 %,62.5MW,195-0046-000; CDS_PHYS_PART_NAME: R_0402-121K,1 %,62.5MW,195-0046-000-121K,195-0046-000; CDS_SEC: 1; DEVICE_TYPENAME: R_0402-121K1625MW195-0046-000-121K195-0046-000; DRAWING: @P3768_A04_LIB.P3768_A04(SCH_1):PAGE14; MAX_WATTAGE: 62.5mW; NV_PN: 195-0046-000; PATH: I244; PHYS_PAGE: 14; PSPICETEMPLATE: X^@REFDES  %1    %2   @NV_PN; ROT: 0; SEC: 1; SIGNAL_MODEL: nv_res; TOL: 1 %; VER: 2; XY: (-4950,5250)
R199 = R: ASSEMBLY: USB3_TYPEA; CDS_LIB: discrete; CDS_PART_NAME: R_0402-10K,5 %,62.5MW,195-0486-000; CDS_PHYS_PART_NAME: R_0402-10K,5 %,62.5MW,195-0486-000-10K,195-0486-000; CDS_SEC: 1; DEVICE_TYPENAME: R_0402-10K5625MW195-0486-000-10K195-0486-000; DRAWING: @P3768_A04_LIB.P3768_A04(SCH_1):PAGE14; MAX_WATTAGE: 62.5mW; NV_PN: 195-0486-000; PATH: I205; PHYS_PAGE: 14; PSPICETEMPLATE: X^@REFDES  %1    %2   @NV_PN; ROT: 0; SEC: 1; SIGNAL_MODEL: nv_res; TOL: 5 %; VER: 2; XY: (-11500,3150)
R200 = R: ASSEMBLY: USB3_TYPEA; CDS_LIB: discrete; CDS_PART_NAME: R_0402-10K,5 %,62.5MW,195-0486-000; CDS_PHYS_PART_NAME: R_0402-10K,5 %,62.5MW,195-0486-000-10K,195-0486-000; CDS_SEC: 1; DEVICE_TYPENAME: R_0402-10K5625MW195-0486-000-10K195-0486-000; DRAWING: @P3768_A04_LIB.P3768_A04(SCH_1):PAGE14; MAX_WATTAGE: 62.5mW; NV_PN: 195-0486-000; PATH: I204; PHYS_PAGE: 14; PSPICETEMPLATE: X^@REFDES  %1    %2   @NV_PN; ROT: 0; SEC: 1; SIGNAL_MODEL: nv_res; TOL: 5 %; VER: 2; XY: (-11250,3150)
R201 = R: ASSEMBLY: USB3_TYPEA; CDS_LIB: discrete; CDS_PART_NAME: R_0402-10K,5 %,62.5MW,195-0486-000; CDS_PHYS_PART_NAME: R_0402-10K,5 %,62.5MW,195-0486-000-10K,195-0486-000; CDS_SEC: 1; DEVICE_TYPENAME: R_0402-10K5625MW195-0486-000-10K195-0486-000; DRAWING: @P3768_A04_LIB.P3768_A04(SCH_1):PAGE14; MAX_WATTAGE: 62.5mW; NV_PN: 195-0486-000; PATH: I202; PHYS_PAGE: 14; PSPICETEMPLATE: X^@REFDES  %1    %2   @NV_PN; ROT: 0; SEC: 1; SIGNAL_MODEL: nv_res; TOL: 5 %; VER: 2; XY: (-11000,3150)
R439 = R#1: ASSEMBLY: 1V1_DCDC; CDS_LIB: discrete; CDS_PART_NAME: R_0402-130OHM,5 %,62.5MW,195-0506-000; CDS_PHYS_PART_NAME: R_0402-130OHM,5 %,62.5MW,195-0506-000-130OHM,195-0506-000; CDS_SEC: 1; CHIPS_PART_NAME: R; DEVICE_TYPENAME: R_0402-130OHM5625MW195-0506-000-130OHM195-0506-000; DRAWING: @P3768_A04_LIB.P3768_A04(SCH_1):PAGE14; MAX_WATTAGE: 62.5mW; NV_PN: 195-0506-000; PATH: I253; PHYS_PAGE: 14; PLACEMENT_NOTE: CoLayout with L10; ROT: 0; SEC: 1; SIGNAL_MODEL: DEFAULT_RESISTOR_0.001OHM_2_1; TOL: 5 %; VER: 1; XY: (-7850,6250)
R440 = R: ASSEMBLY: 1V1_DCDC; CDS_LIB: discrete; CDS_PART_NAME: R_0402-10K,5 %,62.5MW,195-0486-000; CDS_PHYS_PART_NAME: R_0402-10K,5 %,62.5MW,195-0486-000-10K,195-0486-000; CDS_SEC: 1; DEVICE_TYPENAME: R_0402-10K5625MW195-0486-000-10K195-0486-000; DRAWING: @P3768_A04_LIB.P3768_A04(SCH_1):PAGE14; MAX_WATTAGE: 62.5mW; NV_PN: 195-0486-000; PATH: I254; PHYS_PAGE: 14; ROT: 2; SEC: 1; SIGNAL_MODEL: nv_res; SKU: DNI; TOL: 5 %; VER: 2; XY: (-7550,6450)
R441 = R: ASSEMBLY: 1V1_DCDC; CDS_LIB: discrete; CDS_PART_NAME: R_0402-0OHM,0.05 OHM,62.5MW,195-2655-000; CDS_PHYS_PART_NAME: R_0402-0OHM,0.05 OHM,62.5MW,195-2655-000-0OHM,195-2655-000; CDS_SEC: 1; DEVICE_TYPENAME: R_0402-0OHM005OHM625MW195-2655-000-0OHM195-2655-000; DRAWING: @P3768_A04_LIB.P3768_A04(SCH_1):PAGE14; MAX_WATTAGE: 62.5mW; NV_PN: 195-2655-000; PATH: I249; PHYS_PAGE: 14; PLACEMENT_NOTE: CoLayout with L10; ROT: 0; SEC: 1; SIGNAL_MODEL: DEFAULT_RESISTOR_0.001OHM_2_1; TOL: 0.05 ohm; VER: 2; XY: (-6050,5550)
R442 = R: ASSEMBLY: 1V1_DCDC; CDS_LIB: discrete; CDS_PART_NAME: R_0402-10K,5 %,62.5MW,195-0486-000; CDS_PHYS_PART_NAME: R_0402-10K,5 %,62.5MW,195-0486-000-10K,195-0486-000; CDS_SEC: 1; DEVICE_TYPENAME: R_0402-10K5625MW195-0486-000-10K195-0486-000; DRAWING: @P3768_A04_LIB.P3768_A04(SCH_1):PAGE14; MAX_WATTAGE: 62.5mW; NV_PN: 195-0486-000; PATH: I251; PHYS_PAGE: 14; PSPICETEMPLATE: X^@REFDES  %1    %2   @NV_PN; ROT: 0; SEC: 1; SIGNAL_MODEL: nv_res; SKU: DNI; TOL: 5 %; VER: 2; XY: (-5550,6550)
TP50 = LABTESTPOINT: CDS_LIB: electro_mechanic; CDS_PART_NAME: LABTESTPOINT_B28-LABTESTPOINT; CDS_PHYS_PART_NAME: LABTESTPOINT_B28-LABTESTPOINT; CDS_SEC: 1; DEVICE_TYPENAME: LABTESTPOINT_B28-LABTESTPOINT; DRAWING: @P3768_A04_LIB.P3768_A04(SCH_1):PAGE14; PACK_TYPE: B28; PATH: I255; PHYS_PAGE: 14; ROT: 0; SEC: 1; VER: 3; XY: (-7250,6500)
U7 = U_USB_HUB_RTS5489: ASSEMBLY: USB3_TYPEA; CDS_LIB: digital; CDS_PART_NAME: U_USB_HUB_RTS5489_QFN88-RTS5420-GR,USB,115-3110-000; CDS_PHYS_PART_NAME: U_USB_HUB_RTS5489_QFN88-RTS5420-GR,USB,115-3110-000-115-3110-000; CDS_SEC: 1; CaptureCellPackProp: U_USB_HUB_RTS5489A; DEVICE_TYPENAME: U_USB_HUB_RTS5489_QFN88-RTS5420-GRUSB115-3110-000-115-3110-000; DRAWING: @P3768_A04_LIB.P3768_A04(SCH_1):PAGE14; NV_NAME: RTS5420-GR; NV_PN: 115-3110-000; PACK_TYPE: QFN88; PATH: I207; PHYS_PAGE: 14; ROT: 0; SEC: 1; TYPE: USB; VER: 1; XY: (-9100,1450)
U26 = U_OPENVREG_TYPE0: ASSEMBLY: 1V1_DCDC; CDS_LIB: power_supply; CDS_PART_NAME: U_OPENVREG_TYPE0_DFN10-GS7303ACTD-R,BUCK,1PH,1MHZ,NONE,0.6V..3.3V,1%,0.6V,5.5V,3A,2W,316-0703-000; CDS_PHYS_PART_NAME: U_OPENVREG_TYPE0_DFN10-GS7303ACTD-R,BUCK,1PH,1MHZ,NONE,0.6V..3.3V,1%,0.6V,5.5V,3A,2W,316-0703-000-0.6V,316-0703-000; CDS_SEC: 1; DEVICE_TYPENAME: U_OPENVREG_TYPE0_DFN10-GS7303ACTD-RBUCK1PH1MHZNONE06V33V106V55V3A2W316-0703-000-06V316-0703-000; DRAWING: @P3768_A04_LIB.P3768_A04(SCH_1):PAGE14; MAX_CURRENT: 3A; MAX_VOLTAGE: 5.5V; MAX_WATTAGE: 2W; MODE: Buck; NV_NAME: GS7303ACTD-R; NV_PN: 316-0703-000; OUTPUT_VOLTAGE: 0.6V..3.3V; PACK_TYPE: DFN10; PATH: I214; PHASES: 1Ph; PHYS_PAGE: 14; PROGRAMMABLE: None; ROT: 0; SEC: 1; SEC_TYPE: DFN10; SWITCHING_FREQ: 1MHz; TOL: 1%; VER: 1; XY: (-6650,6100)
U28 = U_MEM_FL_SER_256KX8: ASSEMBLY: USB3_TYPEA; CDS_LIB: memory; CDS_PART_NAME: U_MEM_FL_SER_256KX8_SO8-104MHZ,2.3V..3.6V,W25X20CLSVIG-P3768,190-13768-0000-001; CDS_PHYS_PART_NAME: U_MEM_FL_SER_256KX8_SO8-104MHZ,2.3V..3.6V,W25X20CLSVIG-P3768,190-13768-0000-001-190-13768-0000-001; CDS_SEC: 1; DEVICE_TYPENAME: U_MEM_FL_SER_256KX8_SO8-104MHZ23V36VW25X20CLSVIG-P3768190-13768-0000-001-190-13768-0000-001; DRAWING: @P3768_A04_LIB.P3768_A04(SCH_1):PAGE14; NV_NAME: W25X20CLSVIG-P3768; NV_PN: 190-13768-0000-001; PACK_TYPE: SO8; PATH: I274; PHYS_PAGE: 14; POW: 2.3V..3.6V; ROT: 0; SEC: 1; SPEED_GRADE: 104MHz; VER: 1; XY: (-10400,2850)
VS1 = VIRTUAL_SHORT: ASSEMBLY: USB3_TYPEA; CDS_LIB: mechanic; CDS_PART_NAME: VIRTUAL_SHORT_SHUNT-VIRTUAL_SHORT; CDS_PHYS_PART_NAME: VIRTUAL_SHORT_SHUNT-VIRTUAL_SHORT; CDS_SEC: 1; DEVICE_TYPENAME: VIRTUAL_SHORT_SHUNT-VIRTUAL_SHORT; DRAWING: @P3768_A04_LIB.P3768_A04(SCH_1):PAGE14; PACK_TYPE: SHUNT; PATH: I80; PHYS_PAGE: 14; ROT: 0; SEC: 1; VER: 1; XY: (-11050,6950)
VS2 = VIRTUAL_SHORT: ASSEMBLY: USB3_TYPEA; CDS_LIB: mechanic; CDS_PART_NAME: VIRTUAL_SHORT_SHUNT-VIRTUAL_SHORT; CDS_PHYS_PART_NAME: VIRTUAL_SHORT_SHUNT-VIRTUAL_SHORT; CDS_SEC: 1; DEVICE_TYPENAME: VIRTUAL_SHORT_SHUNT-VIRTUAL_SHORT; DRAWING: @P3768_A04_LIB.P3768_A04(SCH_1):PAGE14; PACK_TYPE: SHUNT; PATH: I81; PHYS_PAGE: 14; ROT: 0; SEC: 1; VER: 1; XY: (-11050,6800)
VS3 = VIRTUAL_SHORT: ASSEMBLY: USB3_TYPEA; CDS_LIB: mechanic; CDS_PART_NAME: VIRTUAL_SHORT_SHUNT-VIRTUAL_SHORT; CDS_PHYS_PART_NAME: VIRTUAL_SHORT_SHUNT-VIRTUAL_SHORT; CDS_SEC: 1; DEVICE_TYPENAME: VIRTUAL_SHORT_SHUNT-VIRTUAL_SHORT; DRAWING: @P3768_A04_LIB.P3768_A04(SCH_1):PAGE14; PACK_TYPE: SHUNT; PATH: I82; PHYS_PAGE: 14; ROT: 0; SEC: 1; VER: 1; XY: (-11050,6650)
VS4 = VIRTUAL_SHORT: ASSEMBLY: USB3_TYPEA; CDS_LIB: mechanic; CDS_PART_NAME: VIRTUAL_SHORT_SHUNT-VIRTUAL_SHORT; CDS_PHYS_PART_NAME: VIRTUAL_SHORT_SHUNT-VIRTUAL_SHORT; CDS_SEC: 1; DEVICE_TYPENAME: VIRTUAL_SHORT_SHUNT-VIRTUAL_SHORT; DRAWING: @P3768_A04_LIB.P3768_A04(SCH_1):PAGE14; PACK_TYPE: SHUNT; PATH: I83; PHYS_PAGE: 14; ROT: 0; SEC: 1; VER: 1; XY: (-11050,6500)
VS5 = VIRTUAL_SHORT: ASSEMBLY: USB3_TYPEA; CDS_LIB: mechanic; CDS_PART_NAME: VIRTUAL_SHORT_SHUNT-VIRTUAL_SHORT; CDS_PHYS_PART_NAME: VIRTUAL_SHORT_SHUNT-VIRTUAL_SHORT; CDS_SEC: 1; DEVICE_TYPENAME: VIRTUAL_SHORT_SHUNT-VIRTUAL_SHORT; DRAWING: @P3768_A04_LIB.P3768_A04(SCH_1):PAGE14; PACK_TYPE: SHUNT; PATH: I84; PHYS_PAGE: 14; ROT: 0; SEC: 1; VER: 1; XY: (-11050,6350)
VS6 = VIRTUAL_SHORT: ASSEMBLY: USB3_TYPEA; CDS_LIB: mechanic; CDS_PART_NAME: VIRTUAL_SHORT_SHUNT-VIRTUAL_SHORT; CDS_PHYS_PART_NAME: VIRTUAL_SHORT_SHUNT-VIRTUAL_SHORT; CDS_SEC: 1; DEVICE_TYPENAME: VIRTUAL_SHORT_SHUNT-VIRTUAL_SHORT; DRAWING: @P3768_A04_LIB.P3768_A04(SCH_1):PAGE14; PACK_TYPE: SHUNT; PATH: I86; PHYS_PAGE: 14; ROT: 0; SEC: 1; VER: 1; XY: (-11050,6200)
VS7 = VIRTUAL_SHORT: ASSEMBLY: USB3_TYPEA; CDS_LIB: mechanic; CDS_PART_NAME: VIRTUAL_SHORT_SHUNT-VIRTUAL_SHORT; CDS_PHYS_PART_NAME: VIRTUAL_SHORT_SHUNT-VIRTUAL_SHORT; CDS_SEC: 1; DEVICE_TYPENAME: VIRTUAL_SHORT_SHUNT-VIRTUAL_SHORT; DRAWING: @P3768_A04_LIB.P3768_A04(SCH_1):PAGE14; PACK_TYPE: SHUNT; PATH: I88; PHYS_PAGE: 14; ROT: 0; SEC: 1; VER: 1; XY: (-11050,6050)
VS8 = VIRTUAL_SHORT: ASSEMBLY: USB3_TYPEA; CDS_LIB: mechanic; CDS_PART_NAME: VIRTUAL_SHORT_SHUNT-VIRTUAL_SHORT; CDS_PHYS_PART_NAME: VIRTUAL_SHORT_SHUNT-VIRTUAL_SHORT; CDS_SEC: 1; DEVICE_TYPENAME: VIRTUAL_SHORT_SHUNT-VIRTUAL_SHORT; DRAWING: @P3768_A04_LIB.P3768_A04(SCH_1):PAGE14; PACK_TYPE: SHUNT; PATH: I87; PHYS_PAGE: 14; ROT: 0; SEC: 1; VER: 1; XY: (-11050,5900)
VS9 = VIRTUAL_SHORT: ASSEMBLY: USB3_TYPEA; CDS_LIB: mechanic; CDS_PART_NAME: VIRTUAL_SHORT_SHUNT-VIRTUAL_SHORT; CDS_PHYS_PART_NAME: VIRTUAL_SHORT_SHUNT-VIRTUAL_SHORT; CDS_SEC: 1; DEVICE_TYPENAME: VIRTUAL_SHORT_SHUNT-VIRTUAL_SHORT; DRAWING: @P3768_A04_LIB.P3768_A04(SCH_1):PAGE14; PACK_TYPE: SHUNT; PATH: I89; PHYS_PAGE: 14; ROT: 0; SEC: 1; VER: 1; XY: (-11050,5050)
VS10 = VIRTUAL_SHORT: ASSEMBLY: USB3_TYPEA; CDS_LIB: mechanic; CDS_PART_NAME: VIRTUAL_SHORT_SHUNT-VIRTUAL_SHORT; CDS_PHYS_PART_NAME: VIRTUAL_SHORT_SHUNT-VIRTUAL_SHORT; CDS_SEC: 1; DEVICE_TYPENAME: VIRTUAL_SHORT_SHUNT-VIRTUAL_SHORT; DRAWING: @P3768_A04_LIB.P3768_A04(SCH_1):PAGE14; PACK_TYPE: SHUNT; PATH: I90; PHYS_PAGE: 14; ROT: 0; SEC: 1; VER: 1; XY: (-11050,4900)
VS12 = VIRTUAL_SHORT: ASSEMBLY: USB3_TYPEA; CDS_LIB: mechanic; CDS_PART_NAME: VIRTUAL_SHORT_SHUNT-VIRTUAL_SHORT; CDS_PHYS_PART_NAME: VIRTUAL_SHORT_SHUNT-VIRTUAL_SHORT; CDS_SEC: 1; DEVICE_TYPENAME: VIRTUAL_SHORT_SHUNT-VIRTUAL_SHORT; DRAWING: @P3768_A04_LIB.P3768_A04(SCH_1):PAGE14; PACK_TYPE: SHUNT; PATH: I93; PHYS_PAGE: 14; ROT: 0; SEC: 1; VER: 1; XY: (-11050,4300)
VS13 = VIRTUAL_SHORT: ASSEMBLY: USB3_TYPEA; CDS_LIB: mechanic; CDS_PART_NAME: VIRTUAL_SHORT_SHUNT-VIRTUAL_SHORT; CDS_PHYS_PART_NAME: VIRTUAL_SHORT_SHUNT-VIRTUAL_SHORT; CDS_SEC: 1; DEVICE_TYPENAME: VIRTUAL_SHORT_SHUNT-VIRTUAL_SHORT; DRAWING: @P3768_A04_LIB.P3768_A04(SCH_1):PAGE14; PACK_TYPE: SHUNT; PATH: I94; PHYS_PAGE: 14; ROT: 0; SEC: 1; VER: 1; XY: (-11050,4150)
VS17 = VIRTUAL_SHORT: ASSEMBLY: USB3_TYPEA; CDS_LIB: mechanic; CDS_PART_NAME: VIRTUAL_SHORT_SHUNT-VIRTUAL_SHORT; CDS_PHYS_PART_NAME: VIRTUAL_SHORT_SHUNT-VIRTUAL_SHORT; CDS_SEC: 1; DEVICE_TYPENAME: VIRTUAL_SHORT_SHUNT-VIRTUAL_SHORT; DRAWING: @P3768_A04_LIB.P3768_A04(SCH_1):PAGE14; PACK_TYPE: SHUNT; PATH: I147; PHYS_PAGE: 14; ROT: 0; SEC: 1; VER: 1; XY: (-11050,5750)
VS18 = VIRTUAL_SHORT: ASSEMBLY: USB3_TYPEA; CDS_LIB: mechanic; CDS_PART_NAME: VIRTUAL_SHORT_SHUNT-VIRTUAL_SHORT; CDS_PHYS_PART_NAME: VIRTUAL_SHORT_SHUNT-VIRTUAL_SHORT; CDS_SEC: 1; DEVICE_TYPENAME: VIRTUAL_SHORT_SHUNT-VIRTUAL_SHORT; DRAWING: @P3768_A04_LIB.P3768_A04(SCH_1):PAGE14; PACK_TYPE: SHUNT; PATH: I148; PHYS_PAGE: 14; ROT: 0; SEC: 1; VER: 1; XY: (-11050,5600)
Y1 = XTAL_4PIN: ASSEMBLY: USB3_TYPEA; CDS_LIB: clocks; CDS_PART_NAME: XTAL_4PIN_SMD_32X25-7M12070053,12MHZ,15PPM,2PPM,35PPM,10PF,FUNDAMENTAL,085-0347-000; CDS_PHYS_PART_NAME: XTAL_4PIN_SMD_32X25-7M12070053,12MHZ,15PPM,2PPM,35PPM,10PF,FUNDAMENTAL,085-0347-000-085-0347-000,12MHZ; CDS_SEC: 1; DEVICE_TYPENAME: XTAL_4PIN_SMD_32X25-7M1207005312MHZ15PPM2PPM35PPM10PFFUNDAMENTAL085-0347-000-085-0347-00012MHZ; DRAWING: @P3768_A04_LIB.P3768_A04(SCH_1):PAGE14; LOAD_CAPACITANCE: 10pF; NV_NAME: 7M12070053; NV_PN: 085-0347-000; OVERTONE: Fundamental; PACK_TYPE: SMD_32X25; PATH: I10; PHYS_PAGE: 14; ROT: 0; SEC: 1; TOL: 15ppm; TOL_AGE: 2ppm; TOL_TOTAL: 35ppm; VER: 2; XY: (-1850,5300)

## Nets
5V_LDO: C51.1 C52.1 U7.41(5V_LDO) VS12.2(B) VS13.2(B)
AV10_1: C40.1 U7.1(AV10) VS1.2(B)
AV10_2: C41.1 U7.7(AV10_2) VS2.2(B)
AV10_3: C42.1 U7.16(AV10_3) VS3.2(B)
AV10_4: C43.1 U7.23(AV10_4) VS4.2(B)
AV10_5: C44.1 U7.29(AV10_5) VS5.2(B)
AV10_6: C45.1 U7.35(AV10_6) VS6.2(B)
AV10_7: C46.1 U7.46(AV10_7) VS7.2(B)
AV10_8: C47.1 U7.57(AV10_8) VS8.2(B)
AV10_9: C155.1 U7.72(AV10_9) VS17.2(B)
AV10_10: C252.1 U7.81(AV10_10) VS18.2(B)
AV33_2: C48.1 U7.42(AV33_2) VS9.2(B)
AV33_3: C49.1 U7.85(AV33_3) VS10.2(B)
GND: C40.2 C41.2 C42.2 C43.2 C44.2 C45.2 C46.2 C47.2 C48.2 C49.2 C51.2 C52.2 C55.2 C56.2 C58.2 C61.2 C63.1 C155.2 C163.2 C164.2 C166.2 C167.2 C170.2 C252.2 C357.2 C358.2 C428.2 R35.1 R175.2 R178.2 U7.4(GND1) U7.26(GND2) U7.32(GND3) U7.89(EPAD) U26.4(GND_01) U26.5(GND_02) U26.11(PAD) U28.4(GND) Y1.2 Y1.4 ; also on sheet 1 2 3 4 5 6 7 8 9 10 12 13 14 15 16 17 18 19 21 25
VDD_3V3_SYS: C56.1 C58.1 C170.1 R36.1 R37.1 R38.1 R199.1 R200.1 R201.1 U7.22(AV33_1) U28.8(VCC) VS9.1(A) VS10.1(A) VS12.1(A) VS13.1(A) ; also on sheet 1 2 3 4 5 6 7 8 12 14 15 19 20 21
VDD_5V_SYS: C163.1 C164.1 C357.1 R440.1 R442.1 U26.2(VCC) U26.3(VIN) ; also on sheet 1 2 8 9 10 12 13 14 15 16 17 21
VDD_AV10_HUB: C166.1 C167.1 C358.1 C387.2 L19.2 R176.1 VS1.1(A) VS2.1(A) VS3.1(A) VS4.1(A) VS5.1(A) VS6.1(A) VS7.1(A) VS8.1(A) VS17.1(A) VS18.1(A)
BUCK_1V1_BD: C165.2 R176.2 R177.1
BUCK_1V1_EN: R175.1 R439.2 R440.2 U26.10(EN_FS)
BUCK_1V1_FB: R177.2 R178.1 R441.2 U26.1(FB)
BUCK_1V1_FB_MID: C165.1 R441.1
BUCK_1V1_MODE: C387.1 C428.1 R442.2 U26.8(BOOT)
BUCK_1V1_PG: TP50.1 U26.9(PGOOD)
BUCK_1V1_SW: L19.1 U26.6(SW_01) U26.7(SW_02)
BUCK_3V3_PG: R439.1 ; also on sheet 8 13 14 15
CAM_I2C_SCL: U7.69(SM_CLK) ; also on sheet 7 20
CAM_I2C_SDA: U7.70(SM_DAT) ; also on sheet 7 20
DSP1_DN: U7.50(DSP1_D_N) ; also on sheet 10
DSP1_DP: U7.49(DSP1_D_P) ; also on sheet 10
DSP1_SSRX_N: U7.8(DSP1_RX_N) ; also on sheet 10
DSP1_SSRX_P: U7.9(DSP1_RX_P) ; also on sheet 10
DSP1_SSTX_N: U7.13(DSP1_TX_N) ; also on sheet 10
DSP1_SSTX_P: U7.12(DSP1_TX_P) ; also on sheet 10
DSP2_DN: U7.52(DSP2_D_N) ; also on sheet 10
DSP2_DP: U7.51(DSP2_D_P) ; also on sheet 10
DSP2_SSRX_N: U7.2(DSP2_RX_N) ; also on sheet 10
DSP2_SSRX_P: U7.3(DSP2_RX_P) ; also on sheet 10
DSP2_SSTX_N: U7.6(DSP2_TX_N) ; also on sheet 10
DSP2_SSTX_P: U7.5(DSP2_TX_P) ; also on sheet 10
DSP3_DN: U7.54(DSP3_D_N) ; also on sheet 9
DSP3_DP: U7.53(DSP3_D_P) ; also on sheet 9
DSP3_SSRX_N: U7.30(DSP3_RX_N) ; also on sheet 9
DSP3_SSRX_P: U7.31(DSP3_RX_P) ; also on sheet 9
DSP3_SSTX_N: U7.34(DSP3_TX_N) ; also on sheet 9
DSP3_SSTX_P: U7.33(DSP3_TX_P) ; also on sheet 9
DSP4_DN: U7.56(DSP4_D_N) ; also on sheet 9
DSP4_DP: U7.55(DSP4_D_P) ; also on sheet 9
DSP4_SSRX_N: U7.24(DSP4_RX_N) ; also on sheet 9
DSP4_SSRX_P: U7.25(DSP4_RX_P) ; also on sheet 9
DSP4_SSTX_N: U7.28(DSP4_TX_N) ; also on sheet 9
DSP4_SSTX_P: U7.27(DSP4_TX_P) ; also on sheet 9
HUB_ADC_CAP: C55.1 U7.40(ADC_CAP)
HUB_DSP12_OCP: R38.2 U7.21(DSP1_OCP) U7.62(DSP2_OCP) ; also on sheet 10
HUB_DSP12_PWR_EN: U7.19(DSP1_PWR_EN) U7.64(DSP2_PWR_EN) ; also on sheet 10
HUB_DSP34_OCP: R36.2 U7.20(DSP3_OCP) U7.63(DSP4_OCP) ; also on sheet 9
HUB_DSP34_PWR_EN: U7.18(DSP3_PWR_EN) U7.65(DSP4_PWR_EN) ; also on sheet 9
HUB_PWR_DET: R37.2 U7.36(BPWR_DET) U7.39(LOC_PWR)
HUB_XTAL_IN: C61.1 U7.43(XTLI) Y1.1
HUB_XTAL_OUT: C63.2 U7.44(XTLO) Y1.3
RREF: R35.2 U7.45(RREF)
SNN_5V_IN1: U7.83(5V_IN1)
SNN_5V_IN2: U7.87(5V_IN2)
SNN_HUB_ADC_IN0: U7.37(ADC_IN0)
SNN_HUB_ADC_IN1: U7.38(ADC_IN1)
SNN_HUB_GPIO14: U7.71(GPIO14)
SNN_HUB_I2C_CLK: U7.17(I2C_CLK)
SNN_HUB_I2C_DAT: U7.66(I2C_DAT)
SNN_HUB_I2C_INT_N: U7.67(I2C_INT*)
SNN_HUB_NC01: U7.10(NC1)
SNN_HUB_NC02: U7.11(NC2)
SNN_HUB_NC03: U7.14(NC3)
SNN_HUB_NC04: U7.15(NC4)
SNN_HUB_NC05: U7.75(NC5)
SNN_HUB_NC06: U7.76(NC6)
SNN_HUB_NC07: U7.79(NC7)
SNN_HUB_NC08: U7.80(NC8)
SNN_HUB_NC09: U7.82(NC9)
SNN_HUB_NC10: U7.84(NC10)
SNN_HUB_NC11: U7.86(NC11)
SNN_HUB_NC12: U7.88(NC12)
SNN_HUB_SM_INT_N: U7.68(SM_INT*)
SPI_FL_HLD: R201.2 U28.7(HOLD*)
SPI_FL_WP: R200.2 U28.3(WP*)
SPI_HUB_CS: R199.2 U7.61(SPI_SCS_N) U28.1(CS*)
SPI_HUB_MISO: U7.58(SPI_MISO) U28.2(SO)
SPI_HUB_MOSI: U7.59(SPI_MOSI) U28.5(SI)
SPI_HUB_SCK: U7.60(SPI_SCK) U28.6(SCK)
USB1_AP_N: U7.48(USP_D_N) ; also on sheet 20
USB1_AP_P: U7.47(USP_D_P) ; also on sheet 20
USBSS0_RX_HUB_N: C62.2 U7.73(USP_RX_N)
USBSS0_RX_HUB_P: C60.2 U7.74(USP_RX_P)
USBSS0_TX_HUB_N: U7.78(USP_TX_N) ; also on sheet 19
USBSS0_TX_HUB_P: U7.77(USP_TX_P) ; also on sheet 19
USBSS0_TX_N: C62.1 ; also on sheet 19
USBSS0_TX_P: C60.1 ; also on sheet 19

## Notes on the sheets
sheet 11
- A
- B
- C
- D
- E
- F
- G
- H
- USB3.2 GEN2 HUB x4 PORTS
- DECOUPLING CAPS
- 1V1 DCDC FOR USB HUB
- PULL-UP FOR OCP
- POWER ON/OFF CONTROL
- 1
- 1
- FOR AV10 PINS
- SELF POWER DETECTION
- 12MHz CRYSTAL
- Vin_H > 1.2V
- Rt
- 2
- VOUT=(0.6V)/ (Rb/(Rt+Rb))
- Rb
- 2
- Rt=100k
- Rb=121k
- VOUT=1.095V
- FOR AV33 PINS
- FOR 5V_LDO PIN
- 3
- 3
- SPI FLASH
- 4
- 4
- 5
- 5
- I2CADDR:7'h6A
- NVIDIA CORPORATION
- 2701 SAN TOMAS EXPRESSWAY
- SANTA CLARA, CA 95050, USA
- ASSEMBLY
- <ASSEMBLY_DESCRIPTION>
- PAGE DETAIL
- USB3.1 HUB
- 600-13768-BASE-400
- NV_PN
- ALL NVIDIA DESIGN SPECIFICATIONS, REFERENCE SPECIFICATIONS, REFERENCE BOARDS, FILES, DRAWINGS, DIAGNOSTICS, LISTS AND OTHER DOCUMENTS OR INFORMATION (TOGETHER AND SEPARATELY, 'MATERIALS') ARE BEING PROVIDED 'AS IS'. THE MATERIALS MAY
- P3768-A04
- 14 OF 25
- CONTAIN KNOWN AND UNKNOWN VIOLATIONS OR DEVIATIONS OF INDUSTRY STANDARDS AND SPECIFICATIONS. NVIDIA MAKES NO WARRANTIES, EXPRESSED, IMPLIED, STATUTORY OR OTHERWISE WITH RESPECT TO THE MATERIALS OR OTHERWISE, AND EXPRESSLY DISCLAIMS ALL
- PCB REV
- PAGE
- IMPLIED WARRANTIES INCLUDING, WITHOUT LIMITATION, THE WARRANTIES OF DESIGN, OF NONINFRINGEMENT, MERCHANTABILITY OR FITNESS FOR A PARTICULAR PURPOSE, OR ARISING FROM A COURSE OF DEALING, TRADE USAGE, TRADE PRACTICE, OR INDUSTRY STANDARDS.
- BOM REV
- A
- DATE
- 27-FEB-2023
- A
- B
- C
- D
- E
- F
- G
- H
